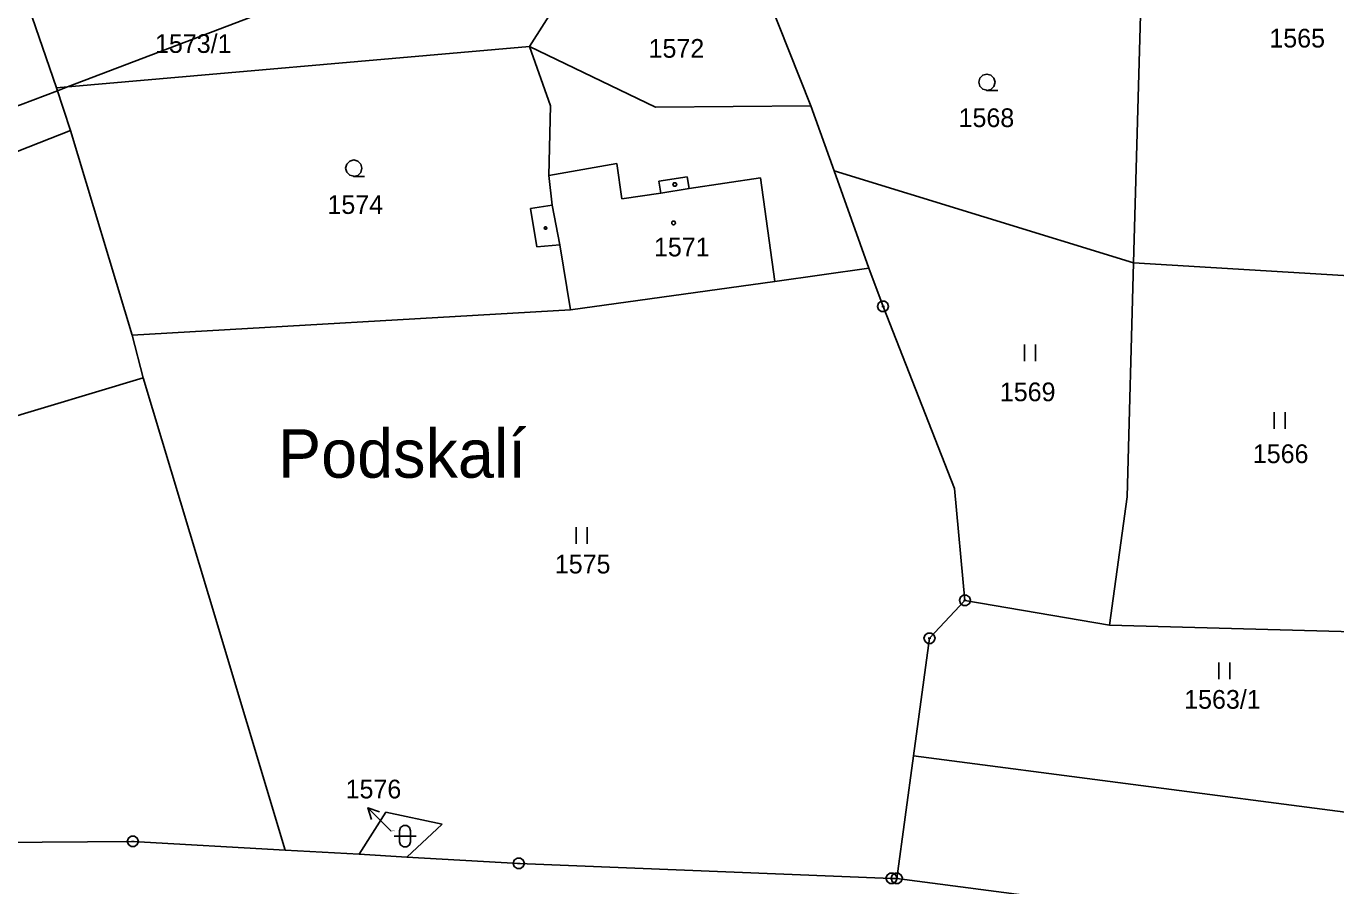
# Model space of a CAD drawing. Extents: x -806774 to -803680, y -1151731 to -1150053.
# Drawn here: x -805690 to -805571, y -1150652 to -1150573.9 of the extents above; entities that cross this region are included whole.
import ezdxf

# ---------------------------------------------------------------- set-up
doc = ezdxf.new("R2010")
doc.units = 0
for name, color, linetype in [('1', 7, 'Continuous'), ('11', 7, 'Continuous'), ('12', 7, 'Continuous'), ('2', 7, 'Continuous'), ('3', 7, 'Continuous'), ('4', 7, 'Continuous'), ('5', 7, 'Continuous'), ('7', 7, 'Continuous'), ('8', 7, 'Continuous')]:
    doc.layers.add(name, color=color, linetype=linetype)

msp = doc.modelspace()

# ---------------------------------------------------------------- linework, layer by layer
at = {"layer": '1'}
for p, q in [((-805644.23, -1150575.69), (-805638.87, -1150567.2)), ((-805623.37, -1150569.23), (-805618.69, -1150581.09)), ((-805687.22, -1150579.45), (-805690.11, -1150571.04)), ((-805589.35, -1150595.34), (-805588.73, -1150572.86)), ((-805687.22, -1150579.45), (-805644.23, -1150575.69)), ((-805644.23, -1150575.69), (-805642.33, -1150581.09)), ((-805644.23, -1150575.69), (-805632.79, -1150581.21)), ((-805685.96, -1150583.32), (-805687.22, -1150579.45)), ((-805642.33, -1150581.09), (-805642.49, -1150587.43)), ((-805632.79, -1150581.21), (-805618.69, -1150581.09)), ((-805618.69, -1150581.09), (-805616.57, -1150587)), ((-805694.1, -1150586.53), (-805685.96, -1150583.32)), ((-805685.96, -1150583.32), (-805680.36, -1150601.92)), ((-805616.57, -1150587), (-805589.35, -1150595.34)), ((-805616.57, -1150587), (-805613.4, -1150595.85)), ((-805642.49, -1150587.43), (-805642.17, -1150590.12)), ((-805642.17, -1150590.12), (-805644.14, -1150590.41)), ((-805644.14, -1150590.41), (-805643.57, -1150593.9)), ((-805641.47, -1150593.73), (-805643.57, -1150593.9)), ((-805640.51, -1150599.62), (-805641.47, -1150593.73)), ((-805589.35, -1150595.34), (-805589.93, -1150616.61)), ((-805589.35, -1150595.34), (-805561.59, -1150597.03)), ((-805613.4, -1150595.85), (-805621.95, -1150597.06)), ((-805613.4, -1150595.85), (-805612.11, -1150599.32)), ((-805640.51, -1150599.62), (-805621.95, -1150597.06)), ((-805680.36, -1150601.92), (-805640.51, -1150599.62)), ((-805612.11, -1150599.32), (-805605.63, -1150615.87)), ((-805680.36, -1150601.92), (-805679.34, -1150605.79)), ((-805698.17, -1150611.46), (-805679.34, -1150605.79)), ((-805679.34, -1150605.79), (-805673.41, -1150625.52)), ((-805605.63, -1150615.87), (-805604.67, -1150626.03)), ((-805589.93, -1150616.61), (-805591.55, -1150628.29)), ((-805673.41, -1150625.52), (-805666.44, -1150648.72)), ((-805604.67, -1150626.03), (-805607.89, -1150629.47)), ((-805604.67, -1150626.03), (-805591.55, -1150628.29)), ((-805591.55, -1150628.29), (-805562.96, -1150629.07)), ((-805609.35, -1150640.16), (-805607.89, -1150629.47)), ((-805610.86, -1150651.29), (-805609.35, -1150640.16)), ((-805569.41, -1150645.37), (-805609.35, -1150640.16)), ((-805657.3, -1150645.28), (-805659.71, -1150649.1)), ((-805657.3, -1150645.28), (-805652.19, -1150646.35)), ((-805652.19, -1150646.35), (-805655.39, -1150649.35)), ((-805727.67, -1150648.26), (-805680.28, -1150647.93)), ((-805666.44, -1150648.72), (-805680.28, -1150647.93)), ((-805659.71, -1150649.1), (-805666.44, -1150648.72)), ((-805655.39, -1150649.35), (-805659.71, -1150649.1)), ((-805645.21, -1150649.93), (-805655.39, -1150649.35)), ((-805611.34, -1150651.29), (-805645.21, -1150649.93)), ((-805610.86, -1150651.29), (-805611.34, -1150651.29)), ((-805573.24, -1150656.2), (-805610.86, -1150651.29))]:
    msp.add_line(p, q, dxfattribs=at)
at = {"layer": '11'}
msp.add_lwpolyline([(-805774, -1150600.5), (-805744.72, -1150597.99), (-805739, -1150597.5), (-805729.96, -1150594.42), (-805690.5, -1150581), (-805687.13, -1150579.72), (-805686.21, -1150579.36), (-805662.62, -1150570.36), (-805635.57, -1150560.04), (-805633.48, -1150559.24), (-805610.18, -1150550.34), (-805589.68, -1150542.52), (-805587, -1150541.5), (-805576.31, -1150536.3), (-805549.76, -1150523.38), (-805549.38, -1150523.2), (-805535.32, -1150516.36), (-805514.91, -1150506.42)], dxfattribs=at)
at = {"layer": '12'}
for p, q in [((-805642.49, -1150587.43), (-805636.3, -1150586.33)), ((-805636.3, -1150586.33), (-805635.85, -1150589.55)), ((-805642.49, -1150587.43), (-805642.17, -1150590.12)), ((-805629.73, -1150588.61), (-805623.25, -1150587.64)), ((-805621.95, -1150597.06), (-805623.25, -1150587.64)), ((-805635.85, -1150589.55), (-805632.32, -1150589.01)), ((-805632.32, -1150589.01), (-805629.73, -1150588.61)), ((-805642.17, -1150590.12), (-805641.47, -1150593.73)), ((-805640.51, -1150599.62), (-805641.47, -1150593.73)), ((-805640.51, -1150599.62), (-805621.95, -1150597.06))]:
    msp.add_line(p, q, dxfattribs=at)
at = {"layer": '3'}
for p, q in [((-805599.25, -1150602.78), (-805599.25, -1150604.28)), ((-805598.25, -1150604.28), (-805598.25, -1150602.78)), ((-805576.57, -1150608.93), (-805576.57, -1150610.43)), ((-805575.57, -1150610.43), (-805575.57, -1150608.93)), ((-805639.99, -1150619.38), (-805639.99, -1150620.88)), ((-805638.99, -1150620.88), (-805638.99, -1150619.38)), ((-805581.59, -1150631.67), (-805581.59, -1150633.17)), ((-805580.59, -1150633.17), (-805580.59, -1150631.67))]:
    msp.add_line(p, q, dxfattribs=at)
for points in [[(-805602.67, -1150579.68), (-805603.05, -1150579.58), (-805603.32, -1150579.31), (-805603.42, -1150578.94), (-805603.32, -1150578.57), (-805603.05, -1150578.3), (-805602.68, -1150578.2), (-805602.31, -1150578.3), (-805602.04, -1150578.57), (-805601.94, -1150578.95), (-805602.04, -1150579.33), (-805602.31, -1150579.6), (-805602.69, -1150579.7), (-805601.69, -1150579.7)], [(-805660.2, -1150587.49), (-805660.58, -1150587.39), (-805660.85, -1150587.12), (-805660.95, -1150586.75), (-805660.85, -1150586.38), (-805660.58, -1150586.11), (-805660.21, -1150586.01), (-805659.84, -1150586.11), (-805659.57, -1150586.38), (-805659.47, -1150586.76), (-805659.57, -1150587.14), (-805659.84, -1150587.41), (-805660.22, -1150587.51), (-805659.22, -1150587.51)], [(-805656.55, -1150647.46), (-805655.28, -1150647.46), (-805654.55, -1150647.46)]]:
    msp.add_lwpolyline(points, dxfattribs=at)
msp.add_lwpolyline([(-805656.05, -1150646.96), (-805655.95, -1150646.67), (-805655.7, -1150646.49), (-805655.39, -1150646.49), (-805655.14, -1150646.67), (-805655.04, -1150646.96), (-805655.04, -1150647.96), (-805655.14, -1150648.25), (-805655.39, -1150648.43), (-805655.7, -1150648.43), (-805655.95, -1150648.25), (-805656.05, -1150647.96)], close=True, dxfattribs=at)
at = {"layer": '4'}
for p, q in [((-805642.49, -1150587.43), (-805636.3, -1150586.33)), ((-805636.3, -1150586.33), (-805635.85, -1150589.55)), ((-805632.48, -1150587.94), (-805629.9, -1150587.54)), ((-805632.32, -1150589.01), (-805632.48, -1150587.94)), ((-805629.9, -1150587.54), (-805629.73, -1150588.61)), ((-805629.73, -1150588.61), (-805623.25, -1150587.64)), ((-805621.95, -1150597.06), (-805623.25, -1150587.64)), ((-805635.85, -1150589.55), (-805632.32, -1150589.01)), ((-805632.32, -1150589.01), (-805629.73, -1150588.61)), ((-805642.17, -1150590.12), (-805641.47, -1150593.73))]:
    msp.add_line(p, q, dxfattribs=at)
at = {"layer": '5'}
for points in [[(-805630.95, -1150588.08), (-805630.86, -1150588.23), (-805630.95, -1150588.38), (-805631.13, -1150588.38), (-805631.22, -1150588.23), (-805631.13, -1150588.08)], [(-805631.15, -1150591.56), (-805631.05, -1150591.58), (-805631, -1150591.67), (-805630.98, -1150591.73), (-805631, -1150591.82), (-805631.08, -1150591.89), (-805631.15, -1150591.9), (-805631.24, -1150591.87), (-805631.3, -1150591.81), (-805631.32, -1150591.73), (-805631.3, -1150591.64), (-805631.22, -1150591.57)], [(-805642.72, -1150592.09), (-805642.66, -1150592.19), (-805642.72, -1150592.29), (-805642.84, -1150592.29), (-805642.9, -1150592.19), (-805642.84, -1150592.09)]]:
    msp.add_lwpolyline(points, close=True, dxfattribs=at)
at = {"layer": '7'}
msp.add_line((-805658.94, -1150644.88), (-805656.82, -1150647), dxfattribs=at)
msp.add_lwpolyline([(-805658.59, -1150645.94), (-805658.94, -1150644.88), (-805657.88, -1150645.23)], dxfattribs=at)
at = {"layer": '8'}
for p, q in [((-805612.23, -1150599.32), (-805611.99, -1150599.32)), ((-805604.79, -1150626.03), (-805604.55, -1150626.03)), ((-805608.01, -1150629.47), (-805607.77, -1150629.47)), ((-805680.4, -1150647.93), (-805680.16, -1150647.93)), ((-805645.33, -1150649.93), (-805645.09, -1150649.93)), ((-805611.46, -1150651.29), (-805611.22, -1150651.29)), ((-805610.98, -1150651.29), (-805610.74, -1150651.29))]:
    msp.add_line(p, q, dxfattribs=at)
for points in [[(-805611.96, -1150598.84), (-805611.71, -1150599.02), (-805611.61, -1150599.31), (-805611.71, -1150599.6), (-805611.96, -1150599.78), (-805612.27, -1150599.78), (-805612.52, -1150599.6), (-805612.62, -1150599.31), (-805612.52, -1150599.02), (-805612.27, -1150598.84)], [(-805604.52, -1150625.55), (-805604.27, -1150625.73), (-805604.17, -1150626.02), (-805604.27, -1150626.31), (-805604.52, -1150626.49), (-805604.83, -1150626.49), (-805605.08, -1150626.31), (-805605.18, -1150626.02), (-805605.08, -1150625.73), (-805604.83, -1150625.55)], [(-805607.74, -1150628.99), (-805607.49, -1150629.17), (-805607.39, -1150629.46), (-805607.49, -1150629.75), (-805607.74, -1150629.93), (-805608.05, -1150629.93), (-805608.3, -1150629.75), (-805608.4, -1150629.46), (-805608.3, -1150629.17), (-805608.05, -1150628.99)], [(-805680.13, -1150647.45), (-805679.88, -1150647.63), (-805679.78, -1150647.92), (-805679.88, -1150648.21), (-805680.13, -1150648.39), (-805680.44, -1150648.39), (-805680.69, -1150648.21), (-805680.79, -1150647.92), (-805680.69, -1150647.63), (-805680.44, -1150647.45)], [(-805645.06, -1150649.45), (-805644.81, -1150649.63), (-805644.71, -1150649.92), (-805644.81, -1150650.21), (-805645.06, -1150650.39), (-805645.37, -1150650.39), (-805645.62, -1150650.21), (-805645.72, -1150649.92), (-805645.62, -1150649.63), (-805645.37, -1150649.45)], [(-805611.19, -1150650.81), (-805610.94, -1150650.99), (-805610.84, -1150651.28), (-805610.94, -1150651.57), (-805611.19, -1150651.75), (-805611.5, -1150651.75), (-805611.75, -1150651.57), (-805611.85, -1150651.28), (-805611.75, -1150650.99), (-805611.5, -1150650.81)], [(-805610.71, -1150650.81), (-805610.46, -1150650.99), (-805610.36, -1150651.28), (-805610.46, -1150651.57), (-805610.71, -1150651.75), (-805611.02, -1150651.75), (-805611.27, -1150651.57), (-805611.37, -1150651.28), (-805611.27, -1150650.99), (-805611.02, -1150650.81)]]:
    msp.add_lwpolyline(points, close=True, dxfattribs=at)

# ---------------------------------------------------------------- texts
at = {"layer": '2'}
for s, height, p in [('1573/1', 1.7, (-805678.27, -1150576.28)), ('1572', 1.7, (-805633.42, -1150576.72)), ('1565', 1.7, (-805577.01, -1150575.79)), ('1568', 1.7, (-805605.25, -1150583.02)), ('1574', 1.7, (-805662.6, -1150590.91)), ('1571', 1.7, (-805632.93, -1150594.77)), ('1569', 1.7, (-805601.5, -1150607.93)), ('1566', 1.7, (-805578.51, -1150613.55)), ('1575', 1.7, (-805641.94, -1150623.58)), ('1563/1', 1.7, (-805584.75, -1150635.87)), ('1576', 0.1, (-805656.8, -1150647))]:
    msp.add_text(s, height=height, dxfattribs=at).set_placement(p)
at = {"layer": '7'}
for s, height, p in [('Podskalí', 4.4, (-805667.1, -1150614.88)), ('1576', 1.7, (-805660.95, -1150644.02))]:
    msp.add_text(s, height=height, dxfattribs=at).set_placement(p)

doc.saveas('drawing.dxf')
